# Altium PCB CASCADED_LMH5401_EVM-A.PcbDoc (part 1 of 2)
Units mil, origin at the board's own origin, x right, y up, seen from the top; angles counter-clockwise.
Board outline 1606 x 1500 mil, 6 copper layers (Top Layer L1, Layer 2 GND L2, Layer 3 V+ L3, Layer 4 V- L4, Layer 5 GND L5, Bottom Layer L6), stack 56.6 mil thick; 98 components, 31 nets, 225 pads, 397 vias.
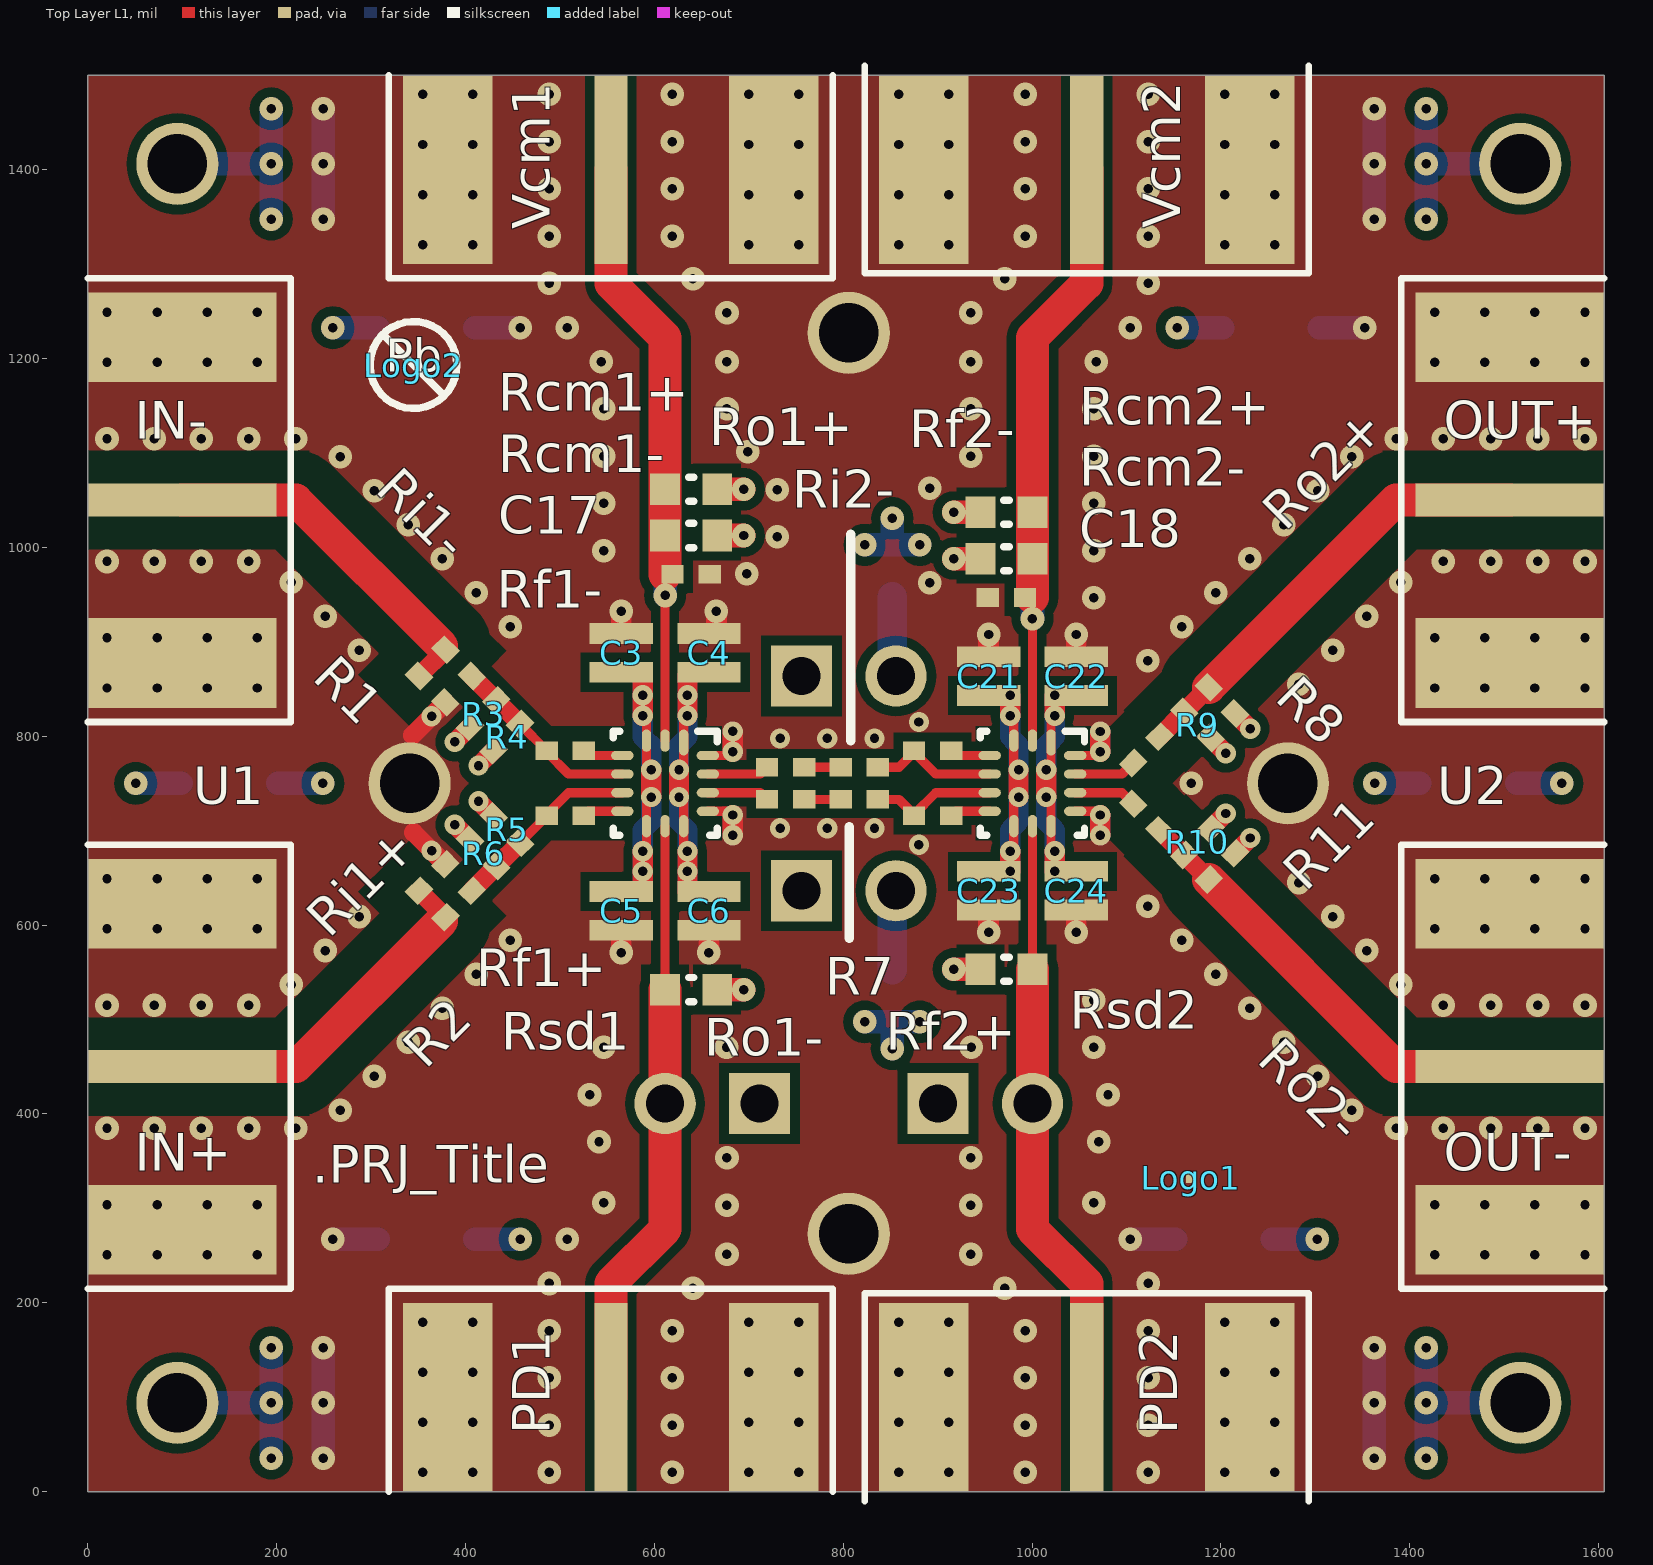
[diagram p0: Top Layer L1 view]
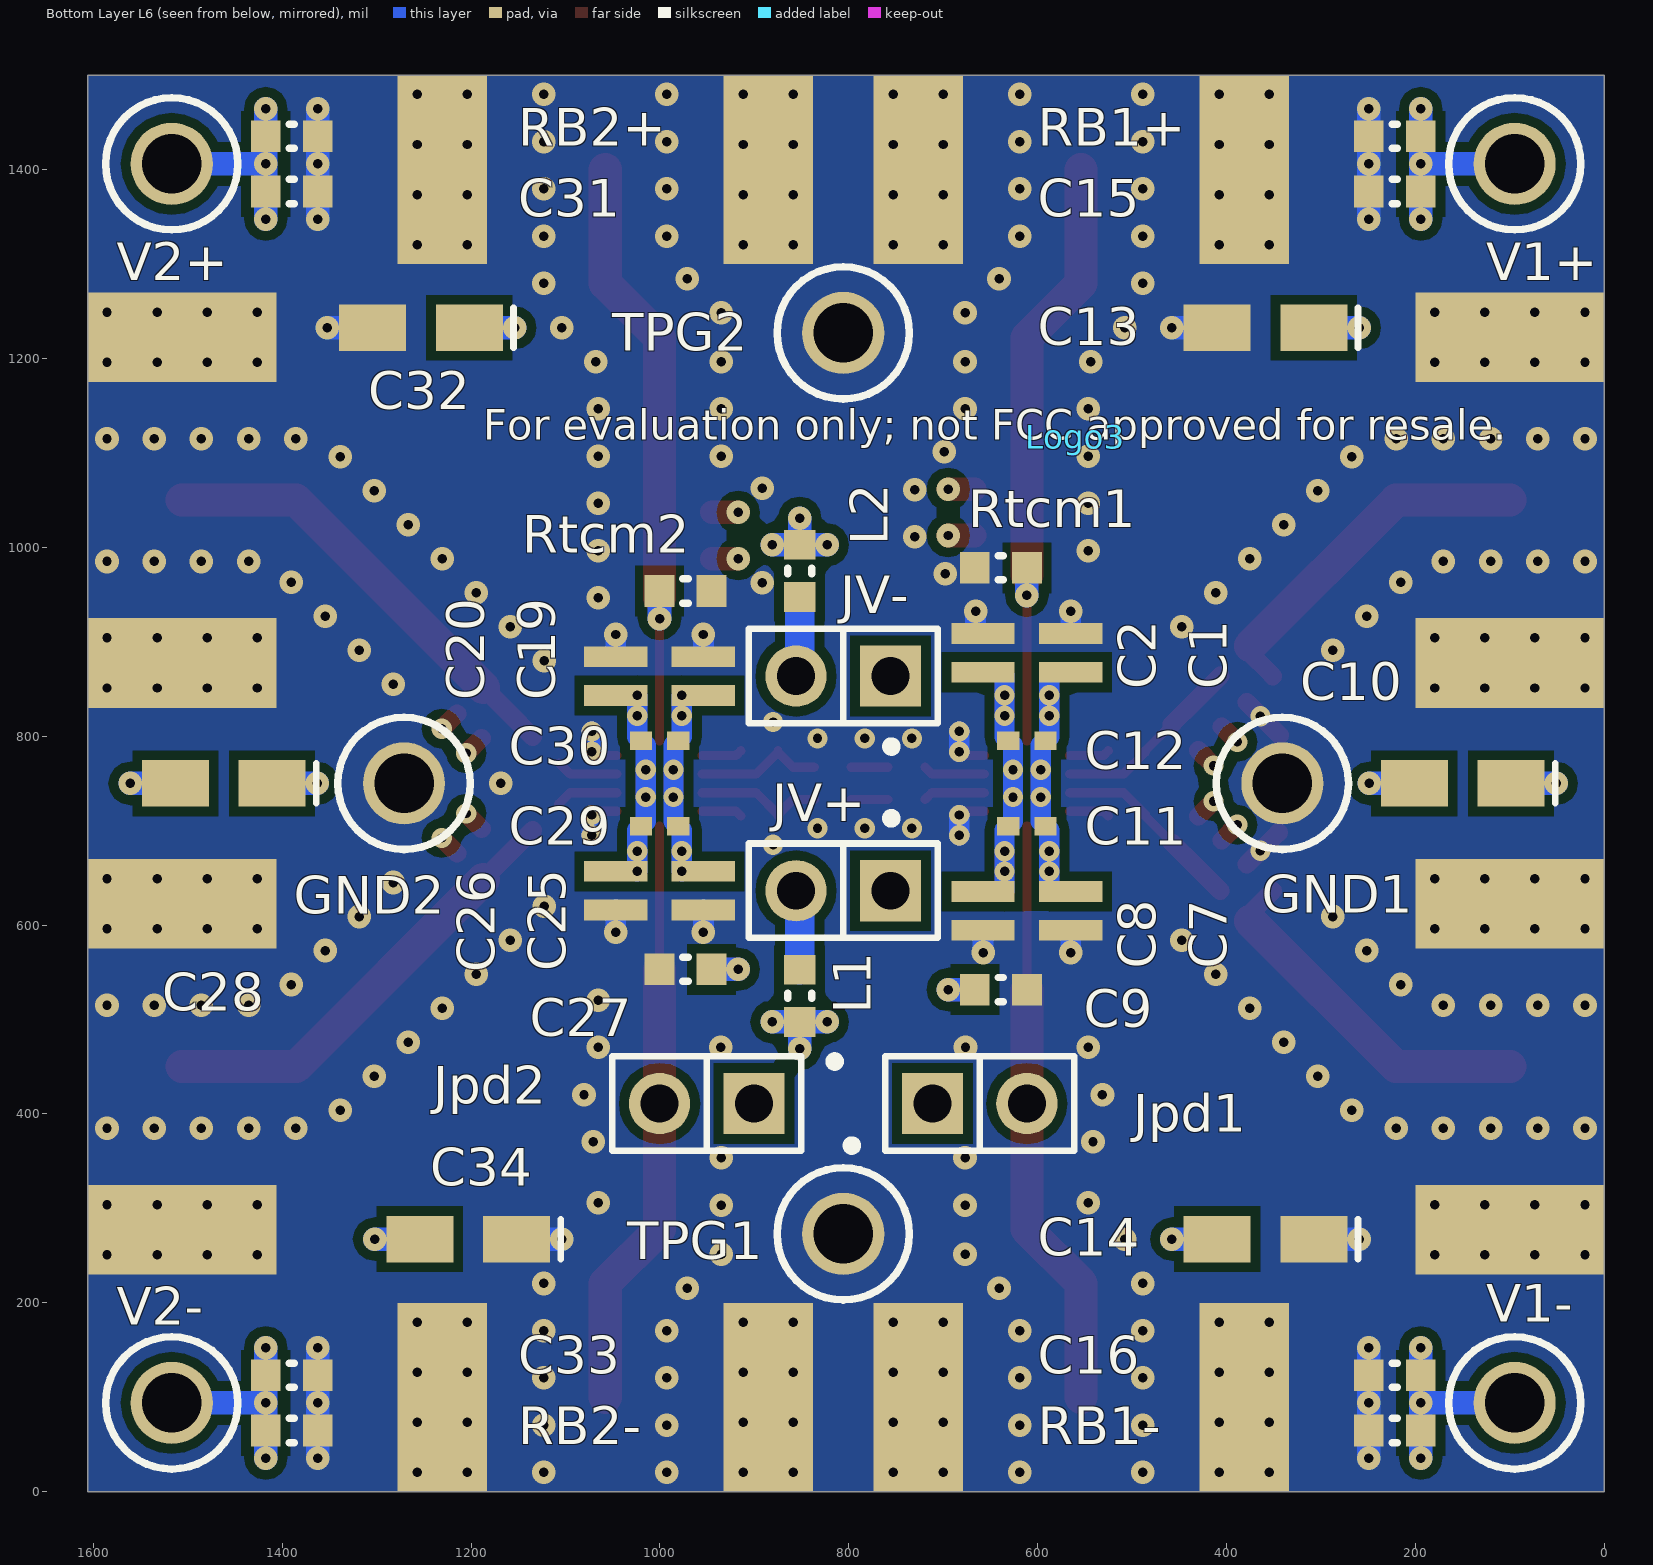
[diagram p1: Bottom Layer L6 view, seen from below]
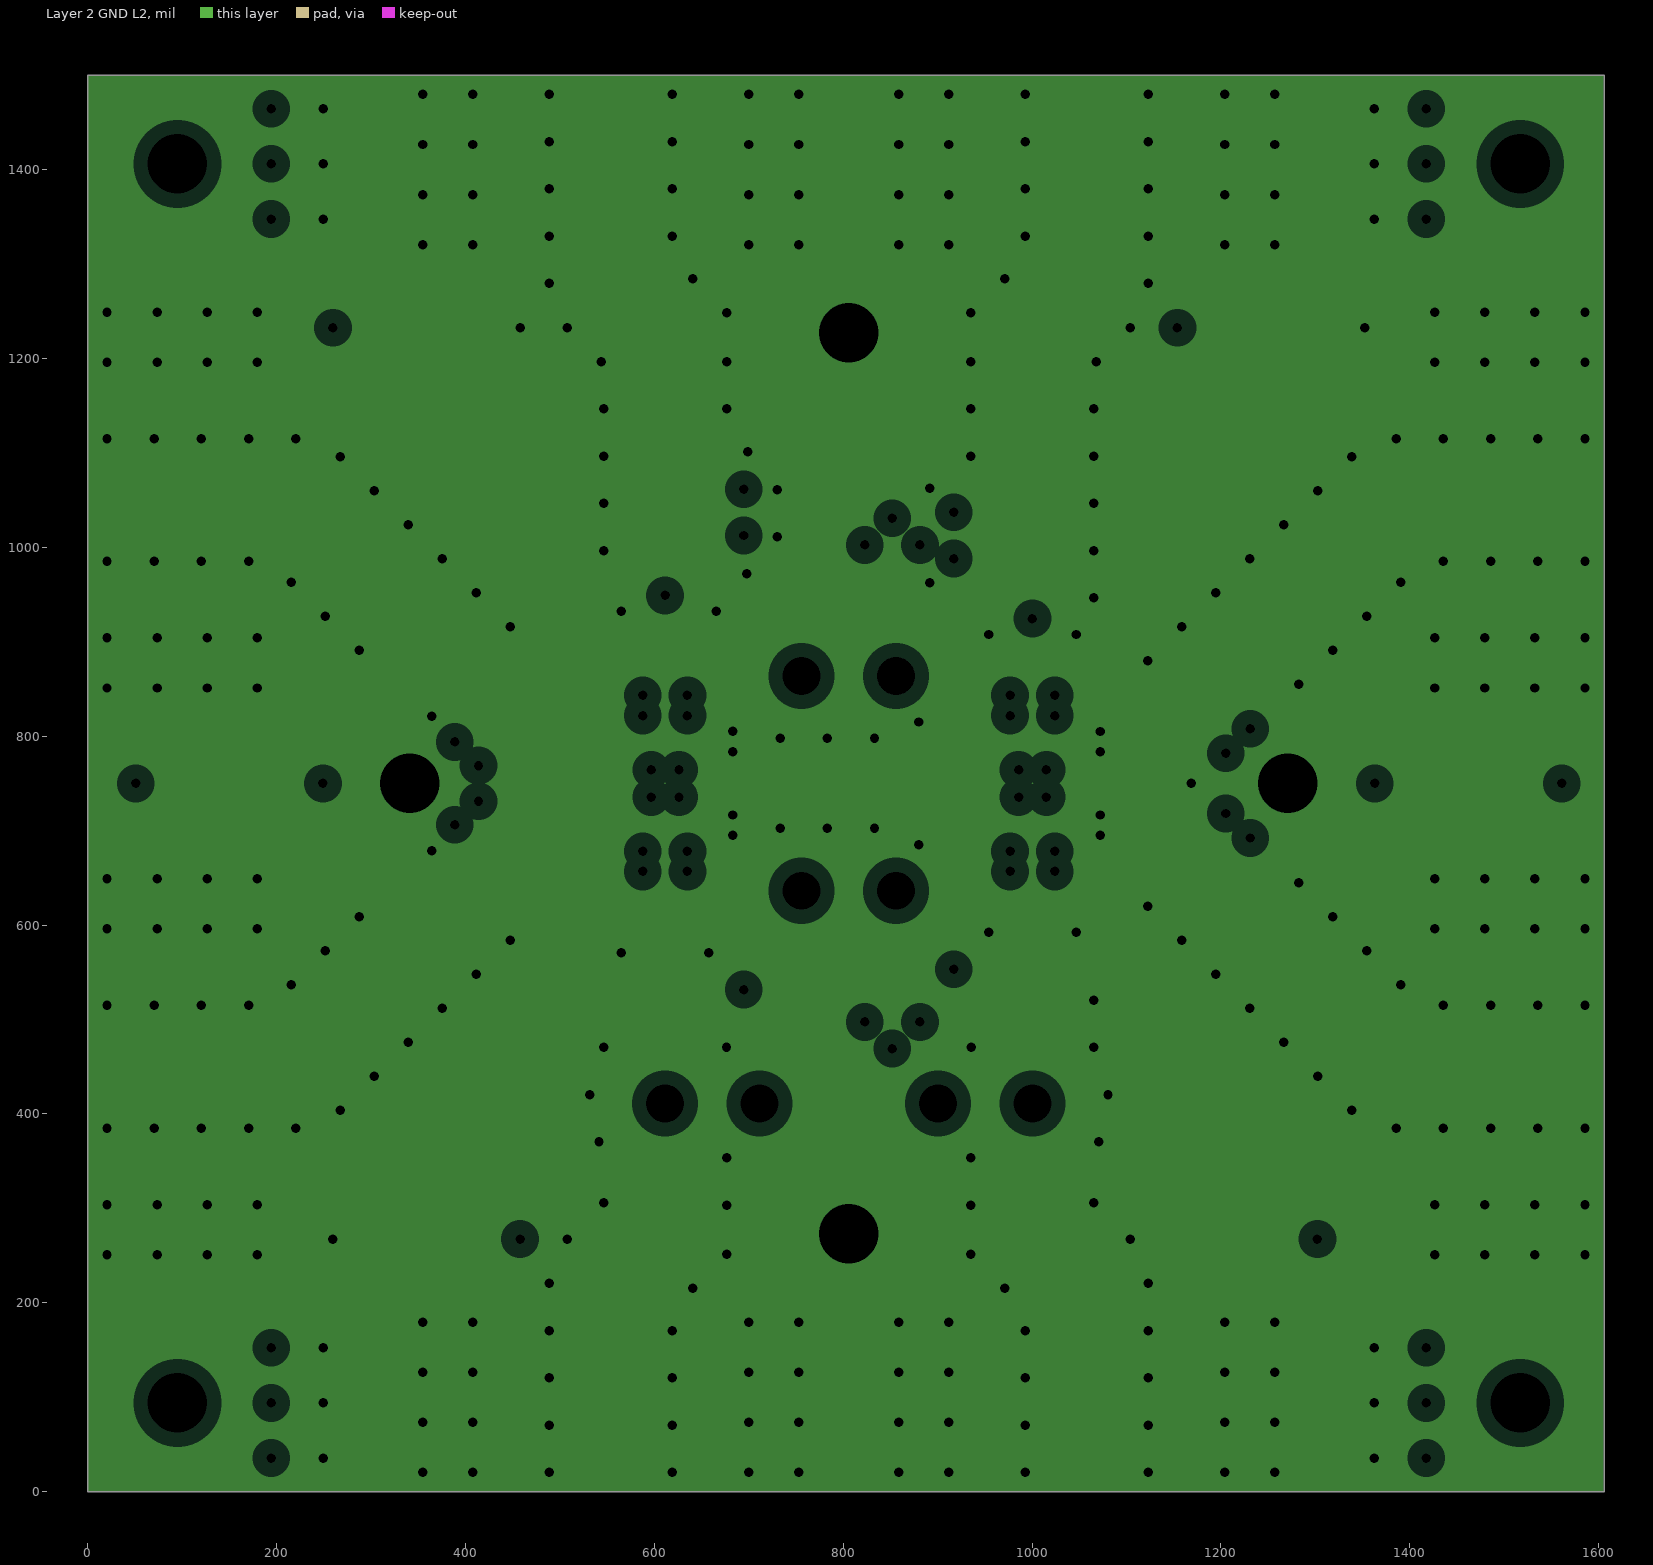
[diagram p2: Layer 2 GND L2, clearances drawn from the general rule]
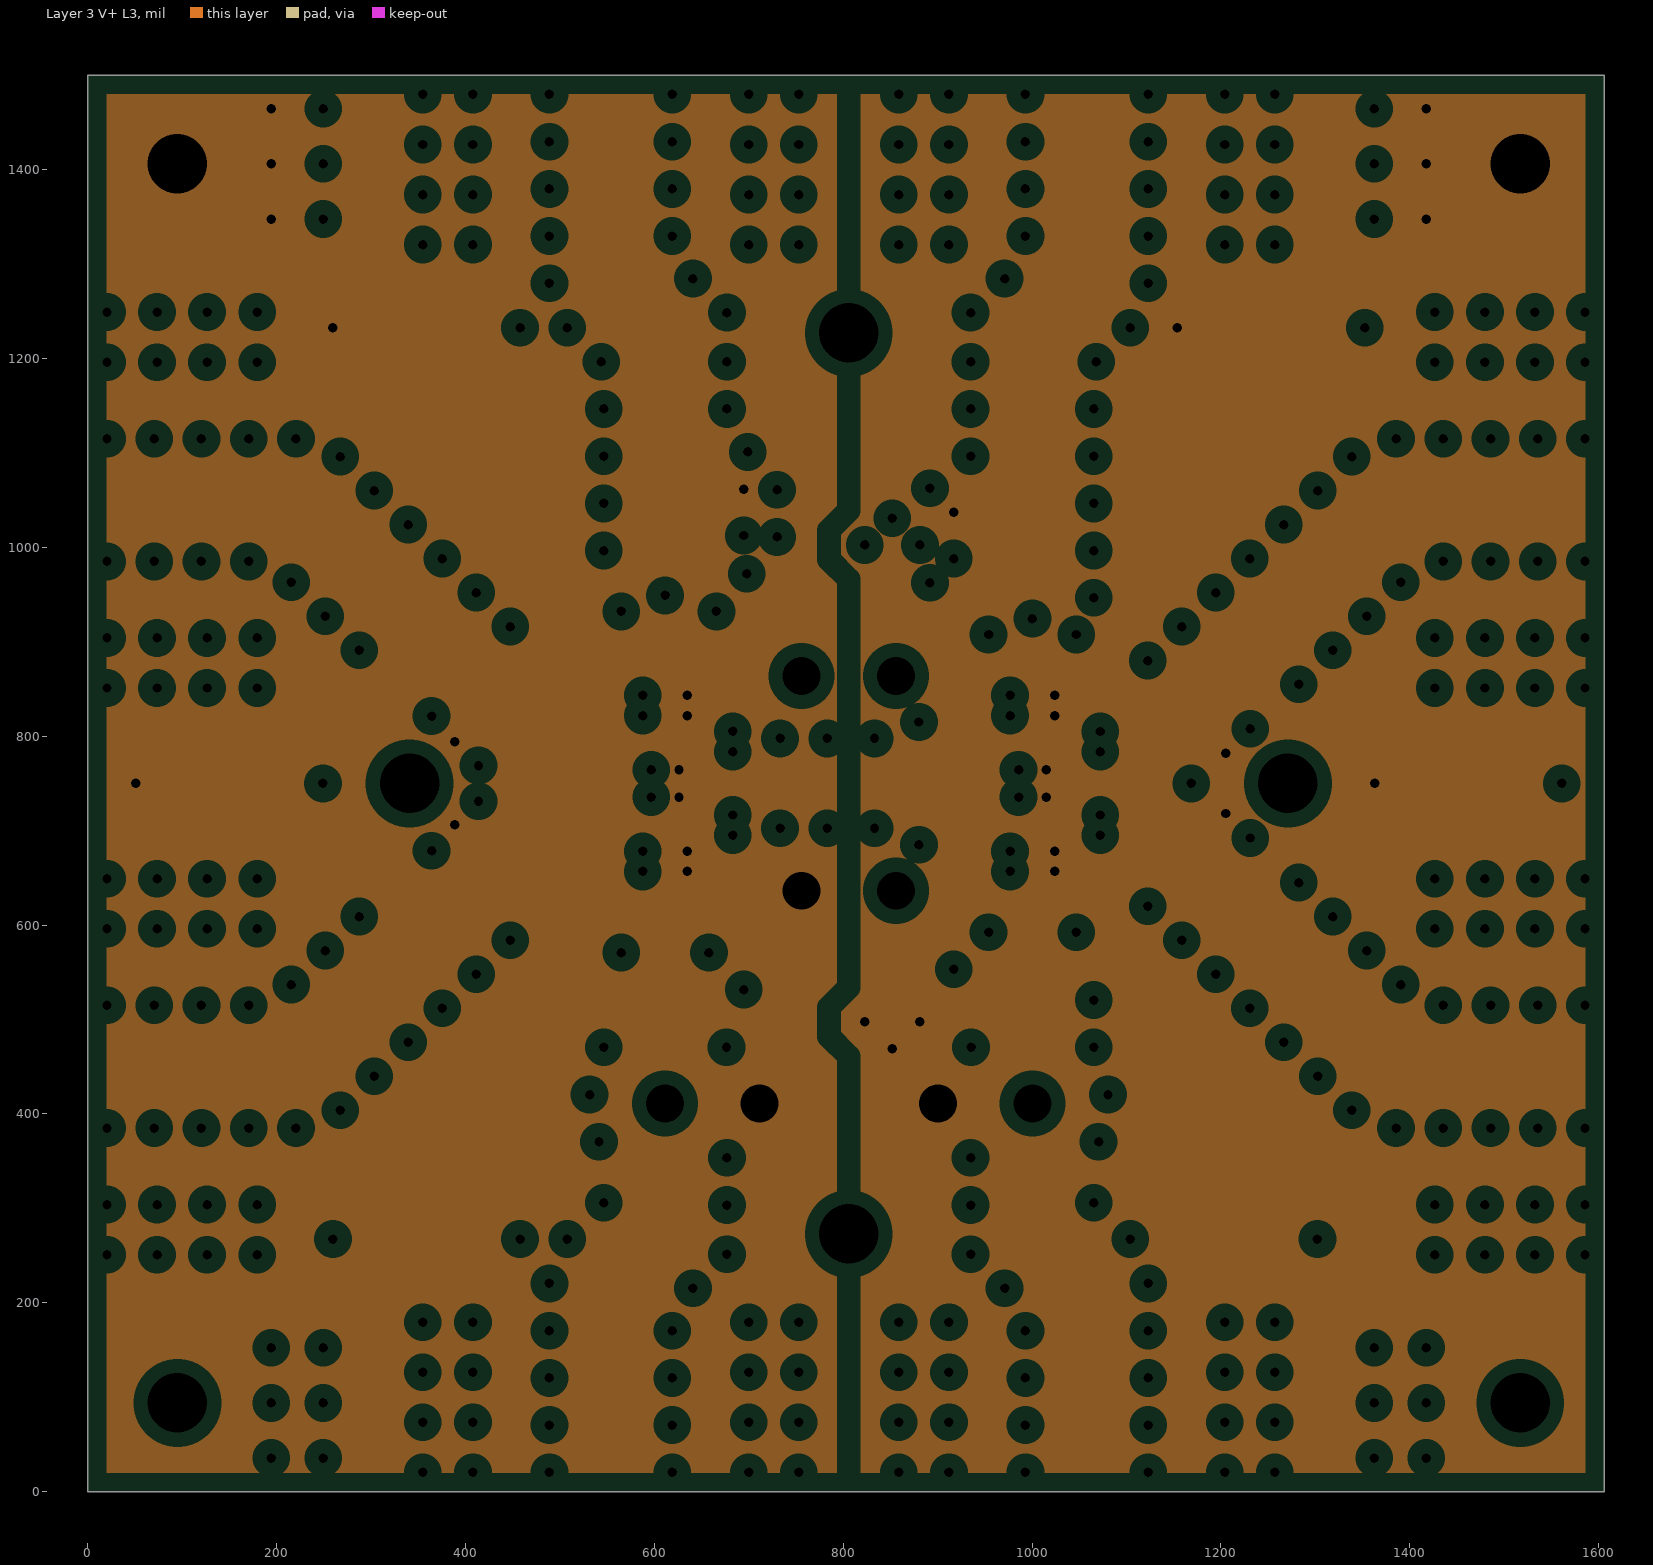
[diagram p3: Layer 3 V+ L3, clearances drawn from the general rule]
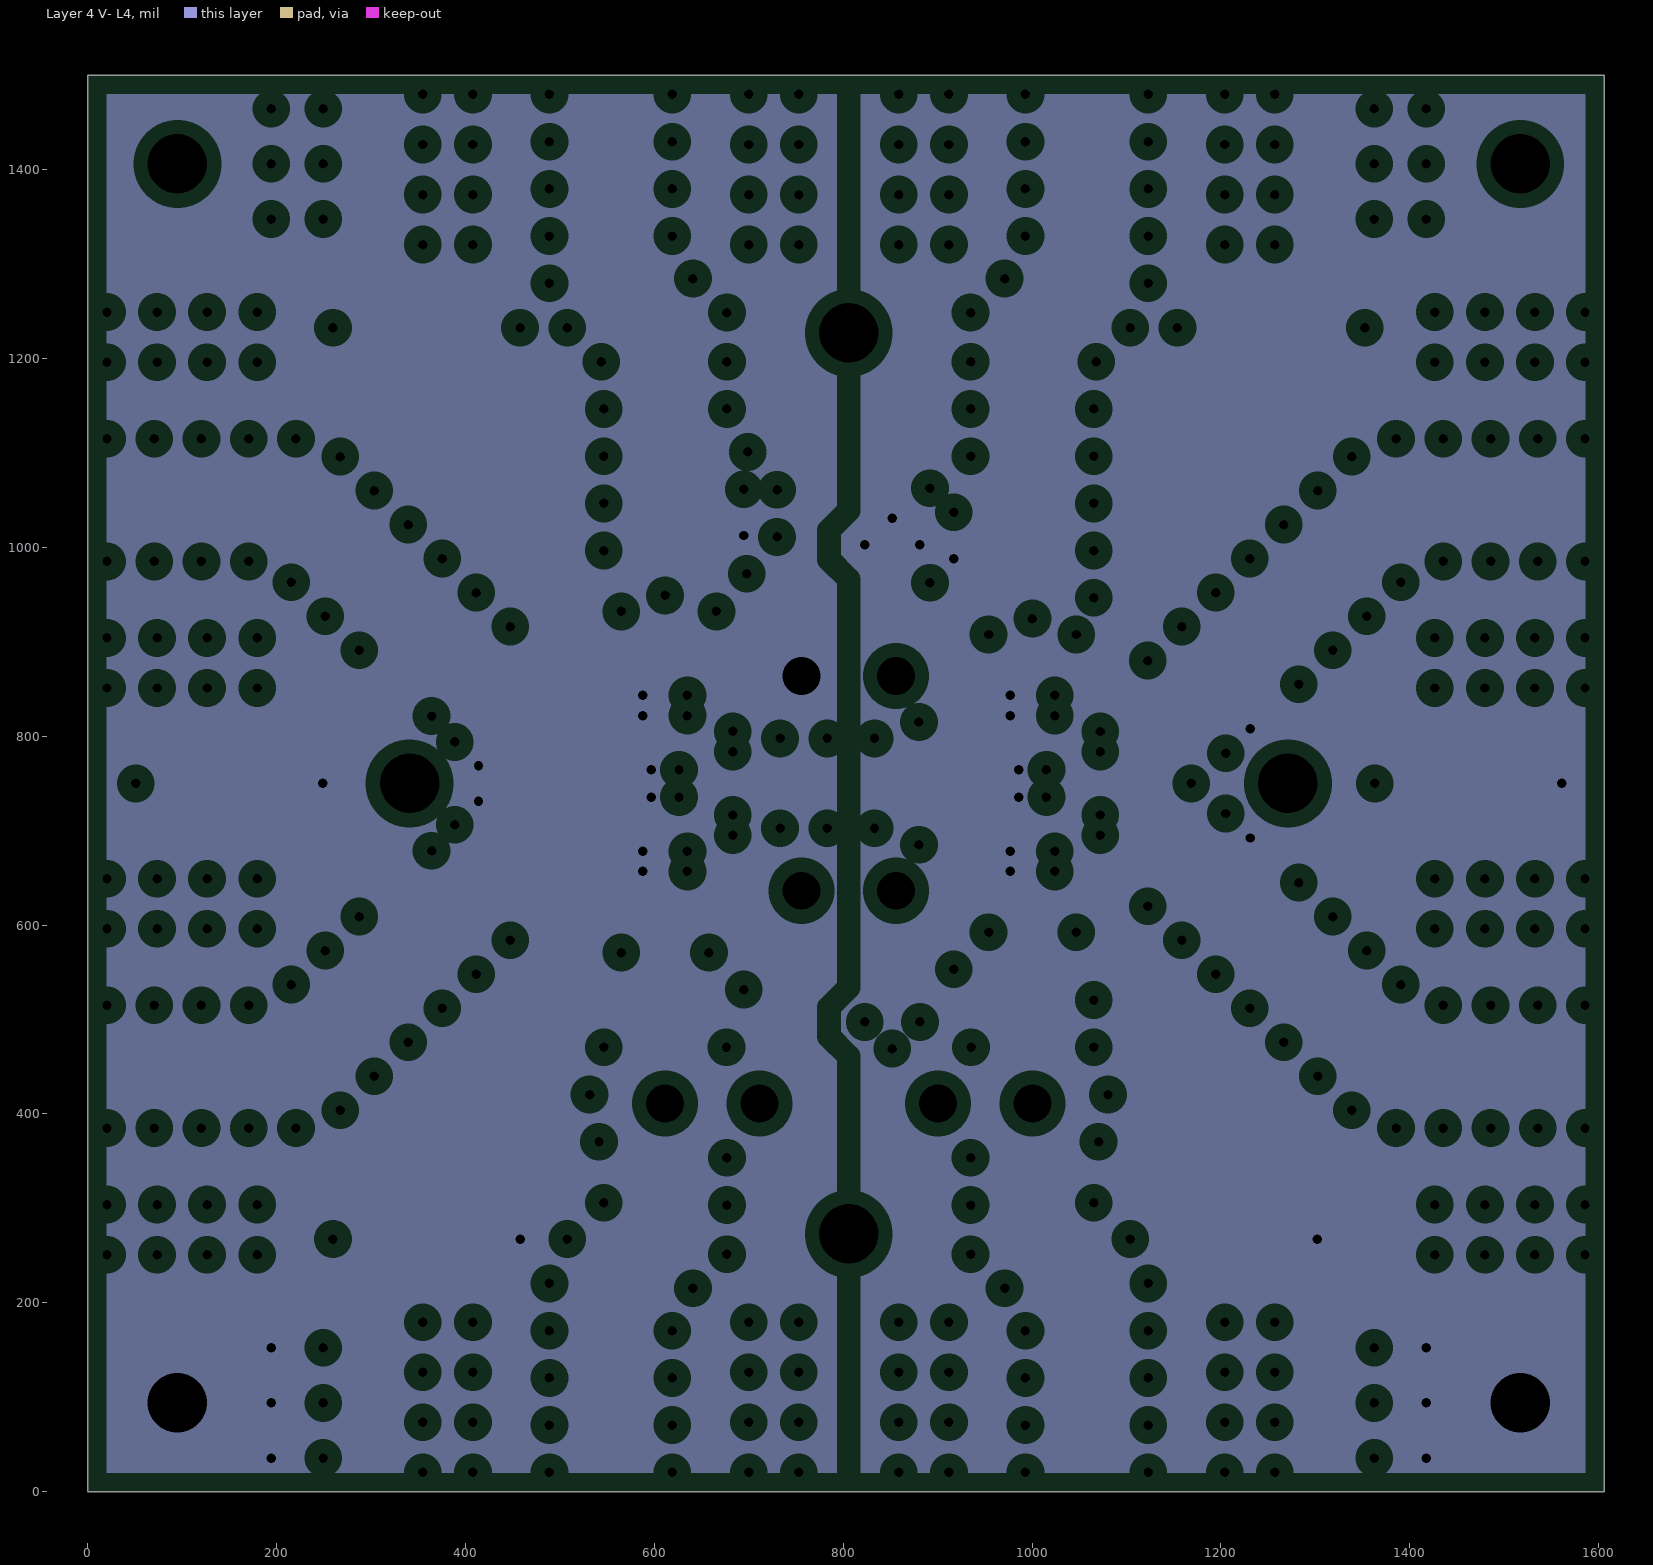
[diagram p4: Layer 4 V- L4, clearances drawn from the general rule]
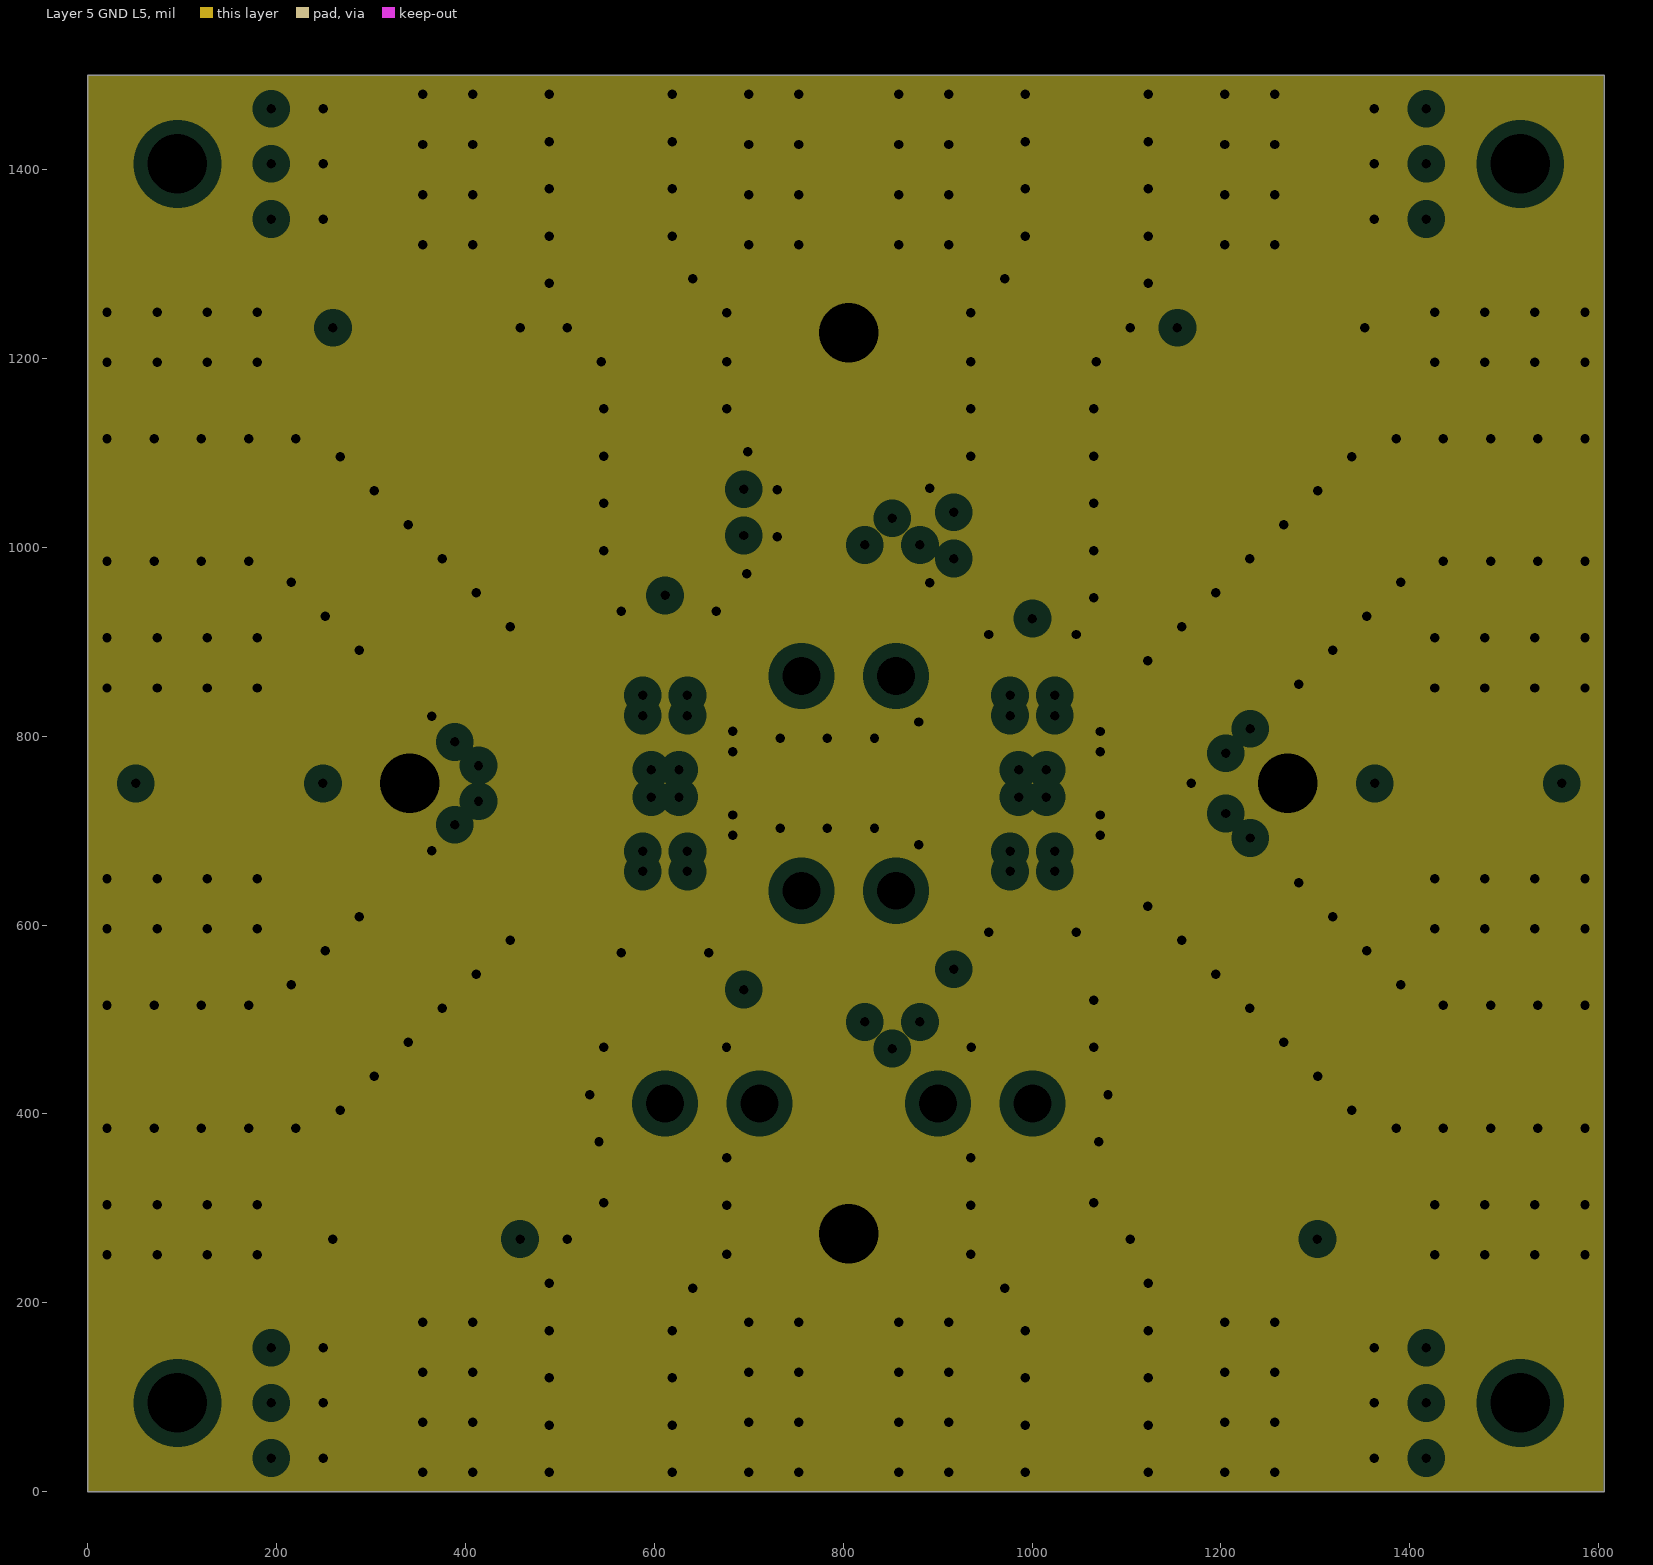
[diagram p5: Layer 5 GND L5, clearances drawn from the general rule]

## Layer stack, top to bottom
Top Solder: solder mask 0.4, Solder Resist, Dk 3.5
Top Layer L1: signal copper 1.4
Dielectric1: core 16.6, Rogers RO4350, Dk 3.66
Layer 2 GND L2: plane copper 1.4, net GND
Dielectric2: prepreg 5, FR406, Dk 4.8
Layer 3 V+ L3: plane copper 1.4, net (Multiple Nets)
Dielectric3: core 5, FR406, Dk 4.8
Layer 4 V- L4: plane copper 1.4, net (Multiple Nets)
Dielectric4: prepreg 5, FR406, Dk 4.8
Layer 5 GND L5: plane copper 1.4, net GND
Dielectric5: core 16.6, FR406, Dk 4.8
Bottom Layer L6: signal copper 1.4
Bottom Solder: solder mask 0.4, Solder Resist, Dk 3.5

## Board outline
0,0 1606,0 1606,1500 0,1500

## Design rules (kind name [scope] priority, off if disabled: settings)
AcuteAngle [All] p1: minimum=4.50000000000000E+0001 checktracksonly=FALSE
AssemblyTestPointUsage [All] p1: valid=2
Clearance Clearance_1 [InNamedPolygon('Top Layer L1-GND') vs (InNet('NetIN+_1') OR InNet('NetIN-_1') OR InNet('NetOUT-_1') OR InNet('NetOUT+_1') OR InNet('NetRtcm_1') OR InNet('NetJpd_2'))] p1: gap=35
Clearance Clearance_BoardEdge_MountingHoles [OnCopper and InComponentClass('Mounting Holes') vs IsKeepOut] p2: gap=40
Clearance Clearance_BoardEdge_Poly [OnCopper and InPoly vs IsKeepOut] p3: gap=25
Clearance Clearance_BoardEdge [OnCopper and Not InComponentClass('Logo') and not InComponentClass('FiducialMark') and not InRegion(1000,500,4000,800) and Not IsKeepout vs IsKeepOut] p4: gap=75
Clearance Clearance_Poly [InPolygon] p5: gap=10
Clearance [All] p6: gap=8
ComponentClearance ComponentClearance_Logo [InComponentClass(Logo)] p1: gap=50 collisioncheckmode=3 verticalgap=10 showdistances=FALSE
ComponentClearance ComponentClearance_ScrewToNut [(HasFootprint('NY PMS 440 0025 PH')) vs (HasFootprint('Keystone_1902C'))] p2: gap=5 collisioncheckmode=3 verticalgap=10 showdistances=FALSE
ComponentClearance ComponentClearance_MountingHoles [InComponentClass('Mounting Holes')] p3: gap=250 collisioncheckmode=3 verticalgap=100000 showdistances=FALSE
ComponentClearance ComponentClearance_SmallPassives [HasFootprint('0201*') or HasFootprint('0402*') or HasFootprint('0508') or HasFootprint('0603*') or HasFootprint('0612') or HasFootprint('0805*') or HasFootprint('0815*') or HasFootprint('0830*') or HasFootprint('1206*') or HasFootprint('1210*') or HasFootprint('1808*') or HasFootprint('1812*') or HasFootprint('1825*') or HasFootprint('2010*') or HasFootprint('2220*') or HasFootprint('2225*') or HasFootprint('2512*') or HasFootprint('2728*') or HasFootprint('3518*') or HasFootprint('3216-18*') or HasFootprint('RMS0014A*') or HasFootprint('0306*') vs HasFootprint('0201*') or HasFootprint('0402*') or HasFootprint('0508') or HasFootprint('0603*') or HasFootprint('0612') or HasFootprint('0805*') or HasFootprint('0815*') or HasFootprint('0830*') or HasFootprint('1206*') or HasFootprint('1210*') or HasFootprint('1808*') or HasFootprint('1812*') or HasFootprint('1825*') or HasFootprint('2010*') or HasFootprint('2220*') or HasFootprint('2225*') or HasFootprint('2512*') or HasFootprint('2728*') or HasFootprint('3518*') or HasFootprint('3216-18*') or HasFootprint('RMS0014A*') or HasFootprint('0306*')] p4: gap=10 collisioncheckmode=3 verticalgap=10 showdistances=FALSE
ComponentClearance ComponentClearance_THtoSMT [IsThruComponent vs IsSMTComponent] p5: gap=10 collisioncheckmode=3 verticalgap=0 showdistances=FALSE
ComponentClearance ComponentClearance_THtoTH [IsThruComponent vs IsThruComponent] p6: gap=35 collisioncheckmode=3 verticalgap=0 showdistances=FALSE
ComponentClearance [All] p7: gap=35 collisioncheckmode=3 verticalgap=10 showdistances=FALSE
DiffPairsRouting [All] p1: maxlimit=100 minlimit=10 mostfreqgap=10 toplayer_minwidth=15 toplayer_maxwidth=15 toplayer_prefwidth=15 bottomlayer_minwidth=15 bottomlayer_maxwidth=15 bottomlayer_prefwidth=15 maxuncoupledlength=1000
FabricationTestPointUsage TestPointUsage [All] p1: valid=2 allowmultiple=FALSE
FabricationTestpoint Testpoint [All] p1: side=3 testpointundercomponent=TRUE minsize=40 maxsize=100 preferedsize=60 minholesize=0 maxholesize=40 preferedholesize=32 testpointgrid=1 allowsidetop=TRUE allowsidebottom=TRUE usegrid=TRUE gridtolerance=0.01
FanoutControl Fanout_LCC [IsLCC] p1: bgadir=Out bgaviamode=Centered fanoutstyle=Auto fanoutdirection=Alternating viagrid=1 // Fanout_LCC (Default Rule)
FanoutControl Fanout_BGA [IsBGA] p2: bgadir=Out bgaviamode=Centered fanoutstyle=Auto fanoutdirection=Alternating viagrid=1 // Fanout_BGA (Default Rule)
FanoutControl Fanout_Default [All] p4: bgadir=Out bgaviamode=Centered fanoutstyle=Auto fanoutdirection=Alternating viagrid=1 // Fanout_Default (Default Rule)
FanoutControl Fanout_Small [(CompPinCount < 5)] p5: bgadir=Out bgaviamode=Centered fanoutstyle=Auto fanoutdirection=OutThenIn viagrid=1 // Fanout_Small (Default Rule)
HoleSize [All] p1: absolutevalues=TRUE maxlimit=251 minlimit=8 maxpercent=80.000 minpercent=20.000
MinimumAnnularRing [All] p1: minimumring=5.73
MinimumSolderMaskSliver MinimumSolderMaskSliver_Logo [InComponentClass('Logo') vs InComponentClass('Logo')] p1: minsoldermaskwidth=0.7
MinimumSolderMaskSliver [All] p2: minsoldermaskwidth=3.84
PlaneClearance [All] p1: clearance=15
PlaneConnect [All] p1: planeconnectstyle=Direct reliefexpansion=10 reliefentries=4 reliefconductorwidth=10 reliefairgap=10
PolygonConnect [All] p1: connectstyle=Direct reliefconductorwidth=10 reliefentries=4 polygonreliefangle="90 Angle" airgapwidth=10
RoutingVias [All] p1: holewidth=16 width=34 viastyle="Through Hole" minholewidth=8 minwidth=21.46 maxholewidth=40 maxwidth=65
SMDToCorner [All] p1: distance=30000
SilkToSilkClearance [All] p1: silktosilkclearance=5
SilkToSolderMaskClearance SilkscreenOverComponentPads [IsPad] p1: minsilkscreentomaskgap=5 clearancetoexposedcopper=TRUE
SolderMaskExpansion [All] p1: expansion=3
UnpouredPolygon [All] p1: allowunpoured=FALSE
Width [All] p1: maxlimit=100 minlimit=8 preferedwidth=10 checkconnectedcopper=TRUE
14 further rules are at their usual default settings.

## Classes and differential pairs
component class Logo: Logo1
component class AssemblyNote: ZZ2 ZZ3 ZZ4
component class 0402L: C12 C17 C18 C30
component class Header: Jpd1 Jpd2 JV+ JV-

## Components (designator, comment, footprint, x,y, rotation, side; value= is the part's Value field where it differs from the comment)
C1 "LLL185R71E103MA01L" 0306 565.02,888.1 r270 bottom
C2 "LLL185R71E103MA01L" 0306 657.86,888.1 r90 bottom
C3 "LLL185R71H222MA01L" 0306 565.02,888.1 r90 top
C4 "LLL185R71H222MA01L" 0306 657.86,888.1 r270 top
C5 "LLL185R71H222MA01L" 0306 565.02,614.9 r270 top
C6 "LLL185R71H222MA01L" 0306 657.86,614.9 r90 top
C7 "LLL185R71E103MA01L" 0306 565.02,614.9 r90 bottom
C8 "LLL185R71E103MA01L" 0306 657.86,614.9 r270 bottom
C9 "GRM188R71C103KA01D" 0603L 639,531.67 r180 bottom
C10 "TPSA106K010R0900" 3216-18 150,750 r0 bottom
C11 "C1005X5R1A104K" 0402L#1 611.44,704.72 r0 bottom
C12 "C1005X7R1E103K" 0402L#1 611.44,795.28 r0 bottom
C13 "TPSA106K010R0900" 3216-18 358.83,1232.5 r0 bottom
C14 "TPSA106K010R0900" 3216-18 358.83,267.5 r0 bottom
C15 "Used in BOM report" 0603L 222,1376.77 r0 bottom
C16 "Used in BOM report" 0603L 222,123.23 r0 bottom
C17 "C1005X7R1E103K" 0402L#1 639,971.33 r180 top
C18 "C1005X7R1E103K" 0402L#1 972.88,946.87 r0 top
C19 "LLL185R71E103MA01L" 0306 954.02,863.64 r270 bottom
C20 "LLL185R71E103MA01L" 0306 1046.86,863.64 r90 bottom
C21 "LLL185R71H222MA01L" 0306 954.02,863.64 r90 top
C22 "LLL185R71H222MA01L" 0306 1046.86,863.64 r270 top
C23 "LLL185R71H222MA01L" 0306 954.02,636.36 r270 top
C24 "LLL185R71H222MA01L" 0306 1046.86,636.36 r90 top
C25 "LLL185R71E103MA01L" 0306 954.02,636.36 r90 bottom
C26 "LLL185R71E103MA01L" 0306 1046.86,636.36 r270 bottom
C27 "GRM188R71C103KA01D" 0603L 972.88,553.13 r0 bottom
C28 "TPSA106K010R0900" 3216-18 1461.88,750 r0 bottom
C29 "C1005X5R1A104K" 0402L#1 1000.44,704.72 r0 bottom
C30 "C1005X7R1E103K" 0402L#1 1000.44,795.28 r0 bottom
C31 "Used in BOM report" 0603L 1389.88,1376.77 r180 bottom
C32 "TPSA106K010R0900" 3216-18 1253.06,1232.5 r0 bottom
C33 "Used in BOM report" 0603L 1389.88,123.23 r180 bottom
C34 "TPSA106K010R0900" 3216-18 1203.06,267.5 r0 bottom
GND1 "5011" Keystone5011 340.88,750 r180 bottom
GND2 "5011" Keystone5011 1271,750 r0 bottom
IN+ "142-0701-851" Emerson_142-0701-851#1 100,450 r90 top
IN- "142-0701-851" Emerson_142-0701-851#1 100,1050 r90 top
Jpd1 "TSW-102-07-G-S" TSW-102-07-G-S 661.44,411 r180 bottom
Jpd2 "TSW-102-07-G-S" TSW-102-07-G-S 950.44,411 r0 bottom
JV+ "TSW-102-07-G-S" TSW-102-07-G-S 805.94,636.36 r0 bottom
JV- "TSW-102-07-G-S" TSW-102-07-G-S 805.94,863.64 r0 bottom
L1 "BLM18SG331TN1D" 0603L 852,525 r270 bottom
L2 "BLM18SG331TN1D" 0603L 852,975 r90 bottom
Logo1 "Texas Instruments" TI_Symbol_SolderMask_Small 1168,332 r0 top
Logo2 "Pb-Free Symbol" Pb-Free_Overlay_Small 345,1193 r0 top
Logo3 "FCC disclaimer" FCC_disclaimer 560,1117 r180 bottom
OUT+ "142-0701-851" Emerson_142-0701-851#1 1506,1050 r270 top
OUT- "142-0701-851" Emerson_142-0701-851#1 1506,450 r270 top
PD1 "142-0701-851" Emerson_142-0701-851#2 553.94,100 r180 top
PD2 "142-0701-851" Emerson_142-0701-851#3 1057.94,-10 r180 top
R1 "CRCW0402137RFKED" 0402L#1 364.84,849.68 r135 top
R2 "CRCW040236R5FKED" 0402L#1 392.88,622.27 r225 top
R3 "Used in BOM report" 0402L#1 418.84,823.93 r225 top
R4 "Used in BOM report" 0402L#1 443.88,798.89 r45 top
R5 "Used in BOM report" 0402L#1 443.88,701.11 r315 top
R6 "Used in BOM report" 0402L#1 418.84,676.07 r135 top
R7 "CRCW04020000Z0ED" 0402L#1 817,733 r180 top
R8 "Used in BOM report" 0402L#2 1201,837.85 r135 top
R9 "Used in BOM report" 0402L#1 1175.05,811.89 r315 top
R10 "Used in BOM report" 0402L#1 1175.05,688.11 r45 top
R11 "Used in BOM report" 0402L#2 1201,662.15 r225 top
RB1+ "Used in BOM report" 0603L 222,1435.23 r180 bottom
RB1- "Used in BOM report" 0603L 222,64.77 r0 bottom
RB2+ "Used in BOM report" 0603L 1389.88,1435.23 r0 bottom
RB2- "Used in BOM report" 0603L 1389.88,64.77 r180 bottom
Rcm1+ "CRCW06031K00FKEA" 0603L 639,1061.46 r0 top
Rcm1- "CRCW06031K00FKEA" 0603L 639,1012.46 r180 top
Rcm2+ "CRCW06031K00FKEA" 0603L 972.88,1037 r180 top
Rcm2- "CRCW06031K00FKEA" 0603L 972.88,988 r0 top
Rf1+ "CRCW0402174RFKED" 0402L#1 505.76,715.55 r180 top
Rf1- "CRCW0402174RFKED" 0402L#1 505.76,784.45 r180 top
Rf2+ "CRCW0402174RFKED" 0402L#1 894.76,715.55 r180 top
Rf2- "CRCW0402174RFKED" 0402L#1 894.76,784.45 r180 top
Ri1+ "CRCW0402137RFKED" 0402L#1 364.84,650.32 r225 top
Ri1- "CRCW040236R5FKED" 0402L#1 392.88,877.73 r315 top
Ri2- "CRCW04020000Z0ED" 0402L#1 817,767 r0 top
Ro1+ "CRCW040240R2FKED" 0402L#1 739,767 r0 top
Ro1- "CRCW040240R2FKED" 0402L#1 739,733 r0 top
Ro2+ "CRCW040240R2FKED" 0402L#1 1120.93,785.61 r45 top
Ro2- "CRCW040240R2FKED" 0402L#1 1120.93,714.39 r315 top
Rsd1 "CRCW060349R9FKEA" 0603L 639,531.67 r180 top
Rsd2 "CRCW060349R9FKEA" 0603L 972.88,553.13 r0 top
Rtcm1 "Used in BOM report" 0603L 639,978.22 r0 bottom
Rtcm2 "Used in BOM report" 0603L 972.88,953.76 r180 bottom
TPG1 "5011" Keystone5011 805.94,273 r180 bottom
TPG2 "5011" Keystone5011 805.94,1227 r180 bottom
U1 "LMH5401IRMSR" RMS0014A 611.44,750 r270 top
U2 "LMH5401IRMSR" RMS0014A 1000.44,750 r270 top
V1+ "5010" Keystone5010 95,1406 r180 bottom
V1- "5014" Keystone5014 95,94 r180 bottom
V2+ "5010" Keystone5010 1516.88,1406 r0 bottom
V2- "5014" Keystone5014 1516.88,94 r180 bottom
Vcm1 "142-0701-851" Emerson_142-0701-851#2 553.94,1400 r0 top
Vcm2 "142-0701-851" Emerson_142-0701-851#3 1057.94,1510 r0 top
ZZ2 "These assemblies are ESD sensitive, ESD precautions shall be observed." AssemblyNote 185,3829.11 r0 top
ZZ3 "These assemblies must be clean and free from flux and all contaminants. Use of no clean flux is not acceptable." AssemblyNote 185,3740.56 r0 top
ZZ4 "These assemblies must comply with workmanship standards IPC-A-610 Class 2., unless otherwise specified." AssemblyNote 185,3652 r0 top

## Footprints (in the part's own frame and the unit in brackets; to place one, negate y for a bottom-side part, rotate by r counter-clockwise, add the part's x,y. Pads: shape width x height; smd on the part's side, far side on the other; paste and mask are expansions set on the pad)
0306 [mil] "bxl footprint"
  rect 22x67 smd: 1(-20.5,0) 2(20.5,0)
  body extent -17,-33 17,33, height 24
0402L#1 [mm] "0402 from SM-752 data"
  rect 0.6x0.5 smd: 1(-0.5,0) 2(0.5,0)
  body extent -0.55,-0.3 0.55,0.3, height 0.6
0402L#2 [mm] "0402 from SM-752 data"
  rect 0.6x0.5 smd mask+0.071: 1(-0.5,0)
  rect 0.6x0.5 smd: 2(0.5,0)
  body extent -0.55,-0.3 0.55,0.3, height 0.6
0603L [mm] "0603 from SM-752 data"
  rect 0.8x0.85 smd: 1(-0.7,0) 2(0.7,0)
  silkscreen extent -0.07,-0.33 0.07,0.33, body extent -0.87,-0.47 0.87,0.47, height 0.85
3216-18 [mm] "Medium density IPC, based on Kemet T495 dimensions"
  rect 1.8x1.25 smd: 1(-1.3,0) 2(1.3,0)
  silkscreen extent -2.49,-0.54 -2.49,0.54, body extent -1.7,-0.9 1.7,0.9, height 1.8
AssemblyNote [mil] "Assembly Note"
Emerson_142-0701-851#1 [mil] "Johnson Components"
  rect 35x200 smd mask+6: 1(0,0)
  rect 95x200 smd: 2(-172.5,0) 3(172.5,0)
  rect 95x200 smd far side: 4(172.5,0) 5(-172.5,0)
  silkscreen extent -235,-115 235,100, body extent -190,-95 190,487, height 155
Emerson_142-0701-851#2 [mil] "Johnson Components"
  rect 35x200 smd: 1(0,0)
  rect 95x200 smd: 2(-172.5,0) 3(172.5,0)
  rect 95x200 smd far side: 4(172.5,0) 5(-172.5,0)
  silkscreen extent -235,-115 235,100, body extent -190,-95 190,487, height 155
Emerson_142-0701-851#3 [mil] "Johnson Components"
  rect 35x200 smd: 1(0,-110)
  rect 95x200 smd: 2(-172.5,-110) 3(172.5,-110)
  rect 95x200 smd far side: 4(172.5,-110) 5(-172.5,-110)
  silkscreen extent -235,-220 235,0, body extent -190,-195 190,387, height 155
FCC_disclaimer [mil]
Keystone5010 [mil] "Keystone Multipurpose loops"
  round 87 hole 63: 1(0,0)
  silkscreen extent -70,-70 70,70, body extent -63,-63 63,62, height 319
Keystone5011 [mil] "Keystone Multipurpose loops"
  round 87 hole 63: 1(0,0)
  silkscreen extent -70,-70 70,70, body extent -63,-63 63,62, height 319
Keystone5014 [mil] "Keystone Multipurpose loops"
  round 87 hole 63: 1(0,0)
  silkscreen extent -70,-70 70,70, body extent -63,-63 63,62, height 319
Pb-Free_Overlay_Small [mil]
  silkscreen extent -46,-46 46,46
RMS0014A [mm] "QFN, Body 2.6x2.6mm, Pitch 0.5mm"
  oval 0.7x0.25 smd mask+0.066: 1(-1.1,0.5)
  oval 0.6x0.25 smd: 2(-1.15,0) 3(-1.15,-0.5) 8(1.15,-0.5) 9(1.15,0) 10(1.15,0.5)
  oval 0.25x0.6 smd: 4(-0.75,-1.15) 5(-0.25,-1.15) 6(0.25,-1.15) 7(0.75,-1.15) 11(0.75,1.15) 12(0.25,1.15) 13(-0.25,1.15) 14(-0.75,1.15)
  silkscreen extent -1.4,-1.4 1.4,1.4, body extent -1.3,-1.3 1.3,1.3, height 0.61
TI_Symbol_SolderMask_Small [mil]
  rect 10x10 smd paste-10 mask-10: 0(0,0)
TSW-102-07-G-S [mm] "Samtec 100mil, 1x2, 230 mil above insulator"
  rect 1.65x1.65 hole 1.016 mask+0: 1(-1.27,0)
  round 1.65 hole 1.016 mask+0: 2(1.27,0)
  silkscreen extent -3.57,-1.27 2.54,1.27, body extent -2.54,-1.27 2.54,1.27, height 8.38

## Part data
C1 C2 C7 C8 C19 C20 C25 C26: "CAP, CERM, 0.01uF, 25V, +/-20%, X7R, 0306"
C3 C4 C5 C6 C21 C22 C23 C24: "CAP, CERM, 2200pF, 50V, +/-20%, X7R, 0306"
C9 C27: "CAP, CERM, 0.01uF, 16V, +/-10%, X7R, 0603"
C10 C13 C14 C28 C32 C34: "CAP, TA, 10uF, 10V, +/-10%, 0.9 ohm, SMD"
C11 C29: "CAP, CERM, 0.1uF, 10V, +/-10%, X5R, 0402"
C12 C17 C18 C30: "CAP, CERM, 0.01uF, 25V, +/-10%, X7R, 0402"
C15 C16 C31 C33: library part Capacitor, "CAP, CERM, xxxF, xxV, [TempCo], xx%, [PackageReference]"
GND1 GND2 TPG1 TPG2: "Test Point, TH, Multipurpose, Black"
IN+ IN- OUT+ OUT- PD1 PD2 Vcm1 Vcm2: "Connector, SMT, End launch SMA 50 ohm"
Jpd1 Jpd2 JV+ JV-: "Header, TH, 100mil, 2x1, Gold plated, 230 mil above insulator"
L1 L2: "Ferrite Bead, 330 ohm @ 100 MHz, 1.5 A, 0603"
Logo1: library part TI_Logo, "Texas Instrument Corporate Signature"
Logo2: library part Pb-Free
Logo3: library part FCC_disclaimer, "FCC_disclaimer"
R1 Ri1+: "RES, 137, 1%, 0.063 W, 0402"
R2 Ri1-: "RES, 36.5, 1%, 0.063 W, 0402"
R3 R4 R5 R6 R8 R9 R10 R11 RB1+ RB1- RB2+ RB2- Rtcm1 Rtcm2: library part Resistor, "RES, xxx ohm, x%, xW, [PackageReference]"
R7 Ri2-: "RES, 0, 5%, 0.063 W, 0402"
Rcm1+ Rcm1- Rcm2+ Rcm2-: "RES, 1.00k ohm, 1%, 0.1W, 0603"
Rf1+ Rf1- Rf2+ Rf2-: "RES, 174, 1%, 0.063 W, 0402"
Ro1+ Ro1- Ro2+ Ro2-: "RES, 40.2 ohm, 1%, 0.063W, 0402"
Rsd1 Rsd2: "RES, 49.9 ohm, 1%, 0.1W, 0603"
U1 U2: "8GHz Ultra Wideband Fully Differential Amplifier, RMS0014A"
V1+ V2+: "Test Point, TH, Multipurpose, Red"
V1- V2-: "Test Point, Multipurpose, Yellow, TH"
ZZ2 ZZ3 ZZ4: library part AssemblyNote

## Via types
v1: diameter 25, hole 10, Top Layer L1 to Bottom Layer L6, tented both sides, 347 vias
v2: diameter 21.46, hole 10, Top Layer L1 to Bottom Layer L6, tented both sides, 50 vias

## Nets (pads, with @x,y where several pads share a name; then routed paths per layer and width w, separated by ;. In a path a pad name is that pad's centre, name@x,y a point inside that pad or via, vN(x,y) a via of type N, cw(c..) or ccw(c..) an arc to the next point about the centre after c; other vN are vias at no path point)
GND: C1.1 C2.2 C3.2 C4.1 C5.2 C6.1 C7.1 C8.2 C9.2 C13.2 C14.1 C15.2 C16.2 C17.1 C18.1 C19.1 C20.2 C21.2 C22.1 C23.2 C24.1 C25.1 C26.2 C27.2 C31.2 C32.2 C33.2 C34.1 GND1.1 GND2.1 IN+.2 IN+.3 IN+.4 IN+.5 IN-.2 IN-.3 IN-.4 IN-.5 Logo1.0 OUT+.2 OUT+.3 OUT+.4 OUT+.5 OUT-.2 OUT-.3 OUT-.4 OUT-.5 PD1.2 PD1.3 PD1.4 PD1.5 PD2.2 PD2.3 PD2.4 PD2.5 R1.1 RB1+.1 RB1-.2 RB2+.1 RB2-.2 Ri1+.1 Rtcm1.2 Rtcm2.2 TPG1.1 TPG2.1 U1.11 U1.14 U2.11 U2.14 Vcm1.2 Vcm1.3 Vcm1.4 Vcm1.5 Vcm2.2 Vcm2.3 Vcm2.4 Vcm2.5 | length 1415.9
  Top Layer L1 w9.84: U1.11@656.72,720.47 679.23,720.47 v2(683.2,716.5) ; U1.14@656.72,779.53 679.23,779.53 v2(683.2,783.5) ; U2.11@1045.72,720.47 1068.23,720.47 v2(1072.2,716.5) ; U2.14@1045.72,779.53 1068.23,779.53 v2(1072.2,783.5)
  Top Layer L1 w19.68: 344,801 R1.1@378.76,835.77 ; 345,698 Ri1+.1@378.76,664.24
  Top Layer L1 w21.46: v2@683.2,695.13 v2(683.2,716.5) ; v2(683.2,783.5) v2@683.2,804.87 ; v2@1072.2,695.13 v2(1072.2,716.5) ; v2(1072.2,783.5) v2@1072.2,804.87
  Top Layer L1 w22: v1(565.02,570.9) C5.2@565.02,594.4 ; C3.2@565.02,908.6 v1(565.02,932.1) ; v1(657.86,570.9) C6.1@657.86,594.4 ; C4.1@665.74,908.6 v1(665.74,932.1) ; v1(954.02,592.36) C23.2@954.02,615.86 ; C21.2@954.02,884.14 v1(954.02,907.64) ; v1(1046.86,592.36) C24.1@1046.86,615.86 ; C22.1@1046.86,884.14 v1(1046.86,907.64)
  Bottom Layer L6 w21.46: v2@683.2,695.13 v2(683.2,716.5) ; v2(683.2,783.5) v2@683.2,804.87 ; v2@1072.2,695.13 v2(1072.2,716.5) ; v2(1072.2,783.5) v2@1072.2,804.87
  Bottom Layer L6 w22: v1(565.02,570.9) C7.1@565.02,594.4 ; C1.1@565.02,908.6 v1(565.02,932.1) ; v1(657.86,570.9) C8.2@657.86,594.4 ; C2.2@665.74,908.6 v1(665.74,932.1) ; v1(954.02,592.36) C25.1@954.02,615.86 ; C19.1@954.02,884.14 v1(954.02,907.64) ; v1(1046.86,592.36) C26.2@1046.86,615.86 ; C20.2@1046.86,884.14 v1(1046.86,907.64)
  Bottom Layer L6 w25: v1(249.56,35.54) RB1-.2@249.56,64.77 v1(249.56,94) C16.2@249.56,123.23 v1(249.56,152.46) ; v1(249.56,1347.54) C15.2@249.56,1376.77 v1(249.56,1406) RB1+.1@249.56,1435.23 v1(249.56,1464.46) ; v1(259.71,267.5) C14.1@307.65,267.5 ; C13.2@410.01,1232.5 v1(457.94,1232.5) ; v1(1103.94,267.5) C34.1@1151.87,267.5 ; C32.2@1304.24,1232.5 v1(1352.17,1232.5) ; v1(1362.32,35.54) RB2-.2@1362.32,64.77 v1(1362.32,94) C33.2@1362.32,123.23 v1(1362.32,152.46) ; v1(1362.32,1347.54) C31.2@1362.32,1376.77 v1(1362.32,1406) RB2+.1@1362.32,1435.23 v1(1362.32,1464.46)
  other v1: 488.94,20.5 618.94,20.5 992.94,20.5 1122.94,20.5 354.94,20.5 407.94,20.5 699.94,20.5 752.94,20.5 858.94,20.5 911.94,20.5 1203.94,20.5 1256.94,20.5 488.94,70.5 618.94,70.5 992.94,70.5 1122.94,70.5 354.94,73.5 407.94,73.5 699.94,73.5 752.94,73.5 858.94,73.5 911.94,73.5 1203.94,73.5 1256.94,73.5 488.94,120.5 618.94,120.5 992.94,120.5 1122.94,120.5 354.94,126.5 407.94,126.5 699.94,126.5 752.94,126.5 858.94,126.5 911.94,126.5 1203.94,126.5 1256.94,126.5 488.94,170.5 618.94,170.5 992.94,170.5 1122.94,170.5 354.94,179.5 407.94,179.5 699.94,179.5 752.94,179.5 858.94,179.5 911.94,179.5 1203.94,179.5 1256.94,179.5 640.94,215.5 970.94,215.5 488.94,220.5 1122.94,220.5 20.5,251 73.5,251 126.5,251 179.5,251 676.94,251.5 934.94,251.5 1426.5,251 1479.5,251 1532.5,251 1585.5,251 507.94,267.5 676.94,303.5 934.94,303.5 20.5,304 73.5,304 126.5,304 179.5,304 1426.5,304 1479.5,304 1532.5,304 1585.5,304 546.44,306 1065.44,306 676.94,353.5 934.94,353.5 541.44,370.5 1070.44,370.5 20.5,385 70.5,385 120.5,385 170.5,385 220.5,385 1385.5,385 1435.5,385 1485.5,385 1535.5,385 1585.5,385 267.5,404 1338.5,404 531.44,420.5 1080.44,420.5 303.5,440 1302.5,440 546.44,470.5 676.44,470.5 935.44,470.5 1065.44,470.5 339.5,476 1266.5,476 375.5,512 1230.5,512 20.5,515 70.5,515 120.5,515 170.5,515 1435.5,515 1485.5,515 1535.5,515 1585.5,515 1065.44,520.5 215.5,537 1390.5,537 411.5,548 1194.5,548 251.5,573 1354.5,573 447.5,584 1158.5,584 20.5,596 73.5,596 126.5,596 179.5,596 1426.5,596 1479.5,596 1532.5,596 1585.5,596 287.5,609 1318.5,609 1122.5,620 1282.5,645 20.5,649 73.5,649 126.5,649 179.5,649 1426.5,649 1479.5,649 1532.5,649 1585.5,649 1168.5,750 20.5,851 73.5,851 126.5,851 179.5,851 1426.5,851 1479.5,851 1532.5,851 1585.5,851 1282.5,855 1122.5,880 287.5,891 1318.5,891 20.5,904 73.5,904 126.5,904 179.5,904 1426.5,904 1479.5,904 1532.5,904 1585.5,904 447.5,916 1158.5,916 251.5,927 1354.5,927 1065.44,946.5 411.5,952 1194.5,952 891.88,962.5 215.5,963 1390.5,963 698,972 20.5,985 70.5,985 120.5,985 170.5,985 1435.5,985 1485.5,985 1535.5,985 1585.5,985 375.5,988 1230.5,988 546.44,996.5 1065.44,996.5 730,1011 339.5,1024 1266.5,1024 546.44,1046.5 1065.44,1046.5 303.5,1060 1302.5,1060 730,1061 891.88,1062.5 267.5,1096 1338.5,1096 546.44,1096.5 934.94,1096.5 1065.44,1096.5 699,1101 20.5,1115 70.5,1115 120.5,1115 170.5,1115 220.5,1115 1385.5,1115 1435.5,1115 1485.5,1115 1535.5,1115 1585.5,1115 546.44,1146.5 676.94,1146.5 934.94,1146.5 1065.44,1146.5 20.5,1196 73.5,1196 126.5,1196 179.5,1196 1426.5,1196 1479.5,1196 1532.5,1196 1585.5,1196 543.94,1196.5 676.94,1196.5 934.94,1196.5 1067.94,1196.5 507.94,1232.5 1103.94,1232.5 20.5,1249 73.5,1249 126.5,1249 179.5,1249 676.94,1248.5 934.94,1248.5 1426.5,1249 1479.5,1249 1532.5,1249 1585.5,1249 488.94,1279.5 1122.94,1279.5 640.94,1284.5 970.94,1284.5 354.94,1320.5 407.94,1320.5 699.94,1320.5 752.94,1320.5 858.94,1320.5 911.94,1320.5 1203.94,1320.5 1256.94,1320.5 488.94,1329.5 618.94,1329.5 992.94,1329.5 1122.94,1329.5 354.94,1373.5 407.94,1373.5 699.94,1373.5 752.94,1373.5 858.94,1373.5 911.94,1373.5 1203.94,1373.5 1256.94,1373.5 488.94,1379.5 618.94,1379.5 992.94,1379.5 1122.94,1379.5 354.94,1426.5 407.94,1426.5 699.94,1426.5 752.94,1426.5 858.94,1426.5 911.94,1426.5 1203.94,1426.5 1256.94,1426.5 488.94,1429.5 618.94,1429.5 992.94,1429.5 1122.94,1429.5 354.94,1479.5 407.94,1479.5 488.94,1479.5 618.94,1479.5 699.94,1479.5 752.94,1479.5 858.94,1479.5 911.94,1479.5 992.94,1479.5 1122.94,1479.5 1203.94,1479.5 1256.94,1479.5
  other v2: 364.21,678.78 880.2,684.98 683.2,695.04 1072.2,695.04 733.2,702.43 783.2,702.43 833.2,702.43 733.2,797.57 783.2,797.57 833.2,797.57 683.2,805.04 1072.2,804.96 880.2,815.02 364.21,821.22
NetC9_1: C9.1 Rsd1.1 | length 56.5
  Top Layer L1 w25: Rsd1.1@666.56,531.67 v1(694.81,531.67)
  Bottom Layer L6 w25: C9.1@666.56,531.67 v1(694.81,531.67)
NetC17_2: C17.2 Rcm1+.1 Rcm1-.2 Rtcm1.1 U1.2 Vcm1.1 | length 633.3
  Top Layer L1 w9.84: U1.2@611.44,795.28 v1@611.44,946.87
  Top Layer L1 w35: Vcm1.1@553.94,1400 553.94,1279.39 611.44,1221.89 Rcm1+.1@611.44,1061.46 C17.2@611.44,971.33
  Bottom Layer L6 w25: v1(611.44,948.99) Rtcm1.1@611.44,978.22
NetC18_2: C18.2 Rcm2+.1 Rcm2-.2 Rtcm2.1 U2.2 Vcm2.1 | length 657.8
  Top Layer L1 w9.84: U2.2@1000.44,795.28 C18.2@1000.44,946.87
  Top Layer L1 w35: C18.2@1000.44,946.87 Rcm2+.1@1000.44,1037 1000.44,1221.89 1057.94,1279.39 Vcm2.1@1057.94,1400
  Bottom Layer L6 w25: v1(1000.44,924.52) Rtcm2.1@1000.44,953.76
NetC27_1: C27.1 Rsd2.1 | length 56.5
  Top Layer L1 w25: v1(917.08,553.13) Rsd2.1@945.32,553.13
  Bottom Layer L6 w25: v1(917.08,553.13) C27.1@945.32,553.13
NetIN+_1: IN+.1 R2.2 Ri1+.2 | length 378.5
  Top Layer L1 w19.68: Ri1+.2@350.92,636.4 R2.2@378.96,608.35
  Top Layer L1 w35: IN+.1@100,450 220.61,450 R2.2@374.89,604.29
NetIN-_1: IN-.1 R1.2 Ri1-.1 | length 378.5
  Top Layer L1 w19.68: R1.2@350.92,863.6 Ri1-.1@378.96,891.65
  Top Layer L1 w35: IN-.1@100,1050 220.61,1050 Ri1-.1@374.89,895.71
NetJpd1_2: Jpd1.2 PD1.1 Rsd1.2 U1.9 | length 628.5
  Top Layer L1 w9.84: Rsd1.2@611.44,531.67 U1.9@611.44,704.72
  Top Layer L1 w35: PD1.1@553.94,100 553.94,220.61 611.44,278.11 Jpd1.2@611.44,411 Rsd1.2@611.44,531.67
NetJpd2_2: Jpd2.2 PD2.1 Rsd2.2 U2.9 | length 628.5
  Top Layer L1 w9.84: Rsd2.2@1000.44,553.13 U2.9@1000.44,704.72
  Top Layer L1 w35: Rsd2.2@1000.44,553.13 Jpd2.2@1000.44,411 1000.44,278.11 1057.94,220.61 PD2.1@1057.94,100
NetJV+_2: JV+.2 L1.1 | length 85.4
  Bottom Layer L6 w31.5: L1.1@852,552.56 852,632.42 JV+.2@855.94,636.36
NetJV-_2: JV-.2 L2.1 | length 85.4
  Bottom Layer L6 w31.5: L2.1@852,947.44 852,867.58 JV-.2@855.94,863.64
NetOUT+_1: OUT+.1 R8.2 R9.1 Ro2+.2 | length 474.9
  Top Layer L1 w19.68: Ro2+.2@1134.85,799.53 R9.1@1161.13,825.81 R8.2@1187.08,851.77
  Top Layer L1 w35: R8.2@1187.08,851.77 1385.32,1050 OUT+.1@1506,1050
NetOUT-_1: OUT-.1 R10.1 R11.2 Ro2-.2 | length 474.9
  Top Layer L1 w19.68: Ro2-.2@1134.85,700.47 R10.1@1161.13,674.19 R11.2@1187.08,648.23
  Top Layer L1 w35: R11.2@1187.08,648.23 1385.32,450 OUT-.1@1506,450
NetR2_1: R2.1 R5.2 R6.1 Rf1+.2 U1.6 | length 203.3
  Top Layer L1 w9.84: R5.2@457.8,687.19 Rf1+.2@486.08,715.47 ; Rf1+.2@486.08,715.55 486.08,717.08 509.16,740.16 U1.6@566.17,740.16
  Top Layer L1 w19.68: R2.1@406.8,636.19 R6.1@432.76,662.15 R5.2@457.8,687.19
NetR3_1: R3.1 R4.2 Rf1-.2 Ri1-.2 U1.5 | length 203.3
  Top Layer L1 w9.84: R4.2@457.8,812.81 Rf1-.2@486.08,784.53 ; Rf1-.2@486.08,784.45 486.08,782.92 509.16,759.84 U1.5@566.17,759.84
  Top Layer L1 w19.68: Ri1-.2@406.8,863.81 R3.1@432.76,837.85 R4.2@457.8,812.81
NetR7_1: R7.1 Rf2+.2 U2.6 | length 136.2
  Top Layer L1 w9.84: R7.1@836.68,733 859.16,733 Rf2+.2@875.08,717.08 ; Rf2+.2@875.08,715.55 Rf2+.2@875.08,717.08 ; U2.6@955.17,740.16 898.16,740.16 Rf2+.2@875.08,717.08
NetR7_2: R7.2 Ro1-.2 | length 38.6
  Top Layer L1 w9.84: Ro1-.2@758.69,733 R7.2@797.31,733
NetRf1+_1: Rf1+.1 U1.7 | length 42.8
  Top Layer L1 w9.84: Rf1+.1@525.45,715.55 530.37,720.47 U1.7@566.17,720.47
NetRf1-_1: Rf1-.1 U1.4 | length 42.8
  Top Layer L1 w9.84: Rf1-.1@525.45,784.45 530.37,779.53 U1.4@566.17,779.53
NetRf2+_1: Rf2+.1 U2.7 | length 42.8
  Top Layer L1 w9.84: Rf2+.1@914.45,715.55 919.37,720.47 U2.7@955.17,720.47
NetRf2-_1: Rf2-.1 U2.4 | length 42.8
  Top Layer L1 w9.84: Rf2-.1@914.45,784.45 919.37,779.53 U2.4@955.17,779.53
NetRf2-_2: Rf2-.2 Ri2-.2 U2.5 | length 136.2
  Top Layer L1 w9.84: Ri2-.2@836.69,767 859.16,767 Rf2-.2@875.08,782.92 ; Rf2-.2@875.08,784.45 Rf2-.2@875.08,782.92 ; U2.5@955.17,759.84 898.16,759.84 Rf2-.2@875.08,782.92
NetRi2-_1: Ri2-.1 Ro1+.2 | length 38.6
  Top Layer L1 w9.84: Ro1+.2@758.69,767 Ri2-.1@797.32,767
NetRo1+_1: Ro1+.1 U1.13 | length 65.6
  Top Layer L1 w9.84: U1.13@656.72,759.84 712.16,759.84 Ro1+.1@719.32,767
NetRo1-_1: Ro1-.1 U1.12 | length 65.6
  Top Layer L1 w9.84: U1.12@656.72,740.16 712.16,740.16 Ro1-.1@719.32,733
NetRo2+_1: Ro2+.1 U2.13 | length 66.2
  Top Layer L1 w9.84: U2.13@1045.72,759.84 1095.16,759.84 Ro2+.1@1107.01,771.69
NetRo2-_1: Ro2-.1 U2.12 | length 66.2
  Top Layer L1 w9.84: U2.12@1045.72,740.16 1095.16,740.16 Ro2-.1@1107.01,728.31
